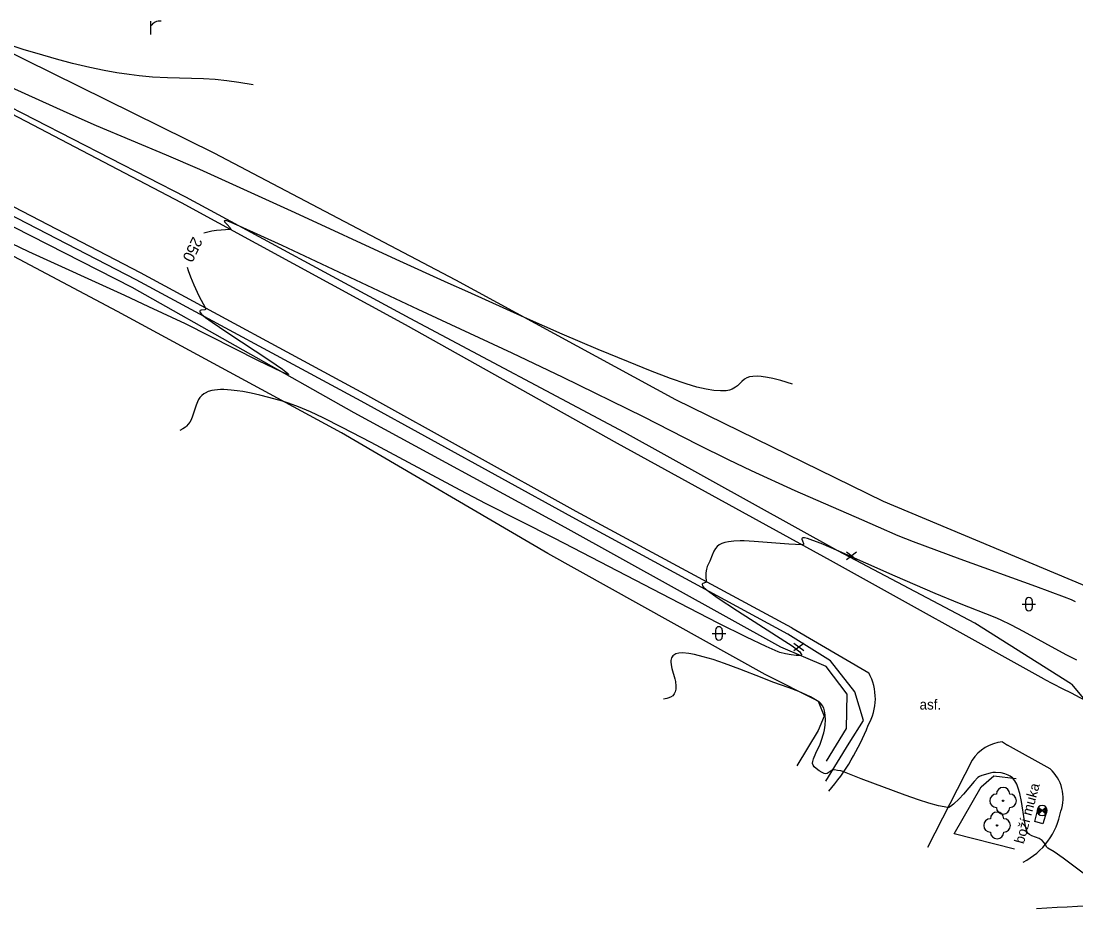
# Model space of a CAD drawing. Extents: x -593772 to -592667, y -1183541 to -1183371.
# Drawn here: x -593084.6 to -593005.8, y -1183525.4 to -1183459.1 of the extents above; entities that cross this region are included whole.
import ezdxf

# ---------------------------------------------------------------- set-up
doc = ezdxf.new("R2010")
doc.units = 0
for name, color, linetype in [('beton', 7, 'Continuous'), ('bez obruby', 7, 'Continuous'), ('hlavni vrstevnice', 7, 'Continuous'), ('popis ploch', 7, 'Continuous'), ('Statni bodove pole', 7, 'Continuous'), ('svisle dopravni znaceni', 7, 'Continuous'), ('terenni hrany', 7, 'Continuous'), ('vrstevnice', 7, 'Continuous'), ('zelen', 7, 'Continuous')]:
    doc.layers.add(name, color=color, linetype=linetype)

msp = doc.modelspace()

# ---------------------------------------------------------------- linework, layer by layer
at = {"layer": 'beton'}
for p, q in [((-593008.84, -1183518.87), (-593008.6, -1183517.98)), ((-593008.6, -1183517.98), (-593007.97, -1183518.14)), ((-593007.97, -1183518.14), (-593008.22, -1183519.03)), ((-593008.22, -1183519.03), (-593008.84, -1183518.87))]:
    msp.add_line(p, q, dxfattribs=at)
at = {"layer": 'bez obruby'}
for p, q in [((-593072.58, -1183472.63), (-593087.95, -1183464.6)), ((-593075.65, -1183477.87), (-593090.83, -1183469.97)), ((-593055.86, -1183481.76), (-593072.58, -1183472.63)), ((-593058.9, -1183486.93), (-593075.65, -1183477.87)), ((-593040, -1183490.61), (-593055.86, -1183481.76)), ((-593043.11, -1183495.69), (-593058.9, -1183486.93)), ((-593024.1, -1183499.36), (-593040, -1183490.61)), ((-593026.99, -1183504.39), (-593043.11, -1183495.69)), ((-593008.13, -1183508.23), (-593024.1, -1183499.36)), ((-593026.99, -1183504.39), (-593021.24, -1183507.75)), ((-593011.25, -1183512.92), (-593010.86, -1183513.16)), ((-593007.69, -1183514.93), (-593010.86, -1183513.16)), ((-593013.51, -1183514.29), (-593016.85, -1183520.8))]:
    msp.add_line(p, q, dxfattribs=at)
for centre, radius, start, end in [((-593024.761, -1183509.679), 4.015, 330.11001, 28.7237), ((-592925.433, -1183350.42), 178.165, 242.34407, 250.07485), ((-593037.691, -1183505.235), 17.631, 319.82198, 338.55864), ((-593010.988, -1183515.902), 2.993, 95.02863, 147.41941), ((-593009.634, -1183517.106), 2.918, 340.09281, 48.23471), ((-593012.168, -1183517.149), 5.363, 297.39756, 349.78246), ((-592999.408, -1183659.031), 133.954, 88.73466, 93.97761)]:
    msp.add_arc(centre, radius, start, end, dxfattribs=at)
at = {"layer": 'hlavni vrstevnice'}
for points in [[(-593005.791, -1183502.447), (-593006.09, -1183502.314), (-593006.613, -1183502.109), (-593008.764, -1183501.317), (-593014.41, -1183499.27), (-593017.885, -1183497.974), (-593019.03, -1183497.516), (-593020.518, -1183496.877), (-593021.746, -1183496.331), (-593026.73, -1183494.149), (-593029.991, -1183492.672), (-593031.72, -1183491.846), (-593033.989, -1183490.71), (-593038.068, -1183488.616), (-593044.076, -1183485.679), (-593047.888, -1183483.859), (-593054.898, -1183480.596), (-593065.077, -1183475.824), (-593068.255, -1183474.375), (-593069.008, -1183474.055), (-593069.21, -1183473.987), (-593069.339, -1183473.964), (-593069.388, -1183473.977), (-593069.395, -1183474.003), (-593069.36, -1183474.073), (-593069.189, -1183474.261), (-593068.944, -1183474.509), (-593068.894, -1183474.589), (-593068.897, -1183474.617), (-593068.963, -1183474.631), (-593069.964, -1183474.712), (-593070.329, -1183474.757), (-593070.729, -1183474.842), (-593070.921, -1183474.903)], [(-593072.164, -1183477.439), (-593072.096, -1183477.678), (-593071.924, -1183478.16), (-593071.672, -1183478.763), (-593071.288, -1183479.582), (-593070.808, -1183480.497), (-593070.788, -1183480.564), (-593070.8, -1183480.602), (-593070.85, -1183480.63), (-593071.13, -1183480.66), (-593071.202, -1183480.691), (-593071.224, -1183480.726), (-593071.225, -1183480.749), (-593071.191, -1183480.827), (-593071.09, -1183480.943), (-593070.789, -1183481.197), (-593070.301, -1183481.553), (-593069.203, -1183482.298), (-593065.978, -1183484.414), (-593065.031, -1183485.074), (-593064.678, -1183485.356), (-593064.601, -1183485.437), (-593064.597, -1183485.464), (-593064.639, -1183485.465), (-593064.844, -1183485.392), (-593065.124, -1183485.265), (-593066.825, -1183484.439), (-593072.302, -1183481.686), (-593075.026, -1183480.404), (-593076.823, -1183479.57), (-593083.995, -1183476.294), (-593085.926, -1183475.381)]]:
    msp.add_lwpolyline(points, dxfattribs=at)
at = {"layer": 'popis ploch'}
for p, q in [((-593074.87, -1183460.06), (-593074.87, -1183459.06)), ((-593009.77, -1183502.63), (-593008.77, -1183502.63)), ((-593009.52, -1183502.38), (-593009.52, -1183502.88)), ((-593009.02, -1183502.38), (-593009.02, -1183502.88)), ((-593032.93, -1183504.81), (-593031.93, -1183504.81)), ((-593032.68, -1183504.56), (-593032.68, -1183505.06)), ((-593032.18, -1183504.56), (-593032.18, -1183505.06))]:
    msp.add_line(p, q, dxfattribs=at)
for centre, radius, start, end in [((-593074.233, -1183459.798), 0.746, 81.32683, 148.70696), ((-593009.271, -1183502.38), 0.25, 0, 180), ((-593009.271, -1183502.88), 0.25, 180, 0), ((-593032.431, -1183504.56), 0.25, 0, 180), ((-593032.431, -1183505.06), 0.25, 180, 0)]:
    msp.add_arc(centre, radius, start, end, dxfattribs=at)
at = {"layer": 'Statni bodove pole'}
for p, q in [((-593008.545, -1183517.785), (-593008.28, -1183518.05)), ((-593008.28, -1183518.05), (-593008.545, -1183518.315)), ((-593008.015, -1183517.785), (-593008.28, -1183518.05)), ((-593008.28, -1183518.05), (-593008.015, -1183518.315))]:
    msp.add_line(p, q, dxfattribs=at)
for radius, start, end in [(0.376, 45, 135), (0.374, 135, 225), (0.304, 135, 225), (0.375, 225, 315), (0.234, 135, 225), (0.164, 135, 225), (0.0944, 135, 225), (0.0244, 135, 225), (0.0244, 315, 45), (0.0944, 315, 45), (0.164, 315, 45), (0.234, 315, 45), (0.304, 315, 45), (0.374, 315, 45)]:
    msp.add_arc((-593008.28, -1183518.05), radius, start, end, dxfattribs=at)
at = {"layer": 'svisle dopravni znaceni'}
for p, q in [((-593022.895, -1183499.281), (-593022.145, -1183498.718)), ((-593022.895, -1183498.718), (-593022.145, -1183499.281)), ((-593026.845, -1183506.101), (-593026.095, -1183505.539)), ((-593026.845, -1183505.539), (-593026.095, -1183506.101))]:
    msp.add_line(p, q, dxfattribs=at)
at = {"layer": 'terenni hrany'}
for p, q in [((-593086.28, -1183460.94), (-593070.17, -1183468.9)), ((-593072.27, -1183472.2), (-593087.77, -1183464.25)), ((-593070.17, -1183468.9), (-593052.12, -1183478.38)), ((-593076.28, -1183478.95), (-593091.61, -1183471.16)), ((-593075.97, -1183478.4), (-593091.16, -1183470.56)), ((-593077.36, -1183480.76), (-593092.47, -1183472.76)), ((-593055.51, -1183481.27), (-593072.27, -1183472.2)), ((-593059.7, -1183488.33), (-593076.28, -1183478.95)), ((-593059.17, -1183487.45), (-593075.97, -1183478.4)), ((-593052.12, -1183478.38), (-593035.68, -1183487.33)), ((-593060.64, -1183489.83), (-593077.36, -1183480.76)), ((-593039.48, -1183489.79), (-593055.51, -1183481.27)), ((-593043.39, -1183496.13), (-593059.17, -1183487.45)), ((-593035.68, -1183487.33), (-593020.17, -1183494.92)), ((-593043.93, -1183496.89), (-593059.7, -1183488.33)), ((-593045.21, -1183498.84), (-593060.64, -1183489.83)), ((-593023.56, -1183498.63), (-593039.48, -1183489.79)), ((-593020.17, -1183494.92), (-593004.23, -1183501.61)), ((-593027.28, -1183504.88), (-593043.39, -1183496.13)), ((-593027.8, -1183505.85), (-593043.93, -1183496.89)), ((-593013.32, -1183504.04), (-593023.56, -1183498.63)), ((-593028.99, -1183507.87), (-593045.21, -1183498.84)), ((-593006.09, -1183508.6), (-593013.32, -1183504.04)), ((-593024.09, -1183506.85), (-593027.28, -1183504.88)), ((-593024.43, -1183507.28), (-593027.8, -1183505.85)), ((-593022.85, -1183509.36), (-593024.43, -1183507.28)), ((-593022.27, -1183509.18), (-593024.09, -1183506.85)), ((-593025.03, -1183509.88), (-593028.99, -1183507.87)), ((-593006.09, -1183508.6), (-593005.07, -1183509.83)), ((-593022.89, -1183511.91), (-593022.85, -1183509.36)), ((-593021.63, -1183511.32), (-593022.27, -1183509.18)), ((-593025.03, -1183509.88), (-593024.58, -1183510.99)), ((-593024.58, -1183510.99), (-593025.01, -1183512.07)), ((-593022.7, -1183513.01), (-593021.63, -1183511.32)), ((-593025.01, -1183512.07), (-593026.61, -1183514.7)), ((-593024.39, -1183514.36), (-593022.89, -1183511.91)), ((-593024.45, -1183515.85), (-593022.7, -1183513.01)), ((-593012.84, -1183516.28), (-593011.9, -1183515.45)), ((-593011.9, -1183515.45), (-593010.23, -1183515.65)), ((-593014.86, -1183519.79), (-593012.84, -1183516.28)), ((-593010.36, -1183520.94), (-593014.86, -1183519.79))]:
    msp.add_line(p, q, dxfattribs=at)
at = {"layer": 'vrstevnice'}
for points in [[(-593067.233, -1183463.815), (-593068.302, -1183463.632), (-593069.213, -1183463.507), (-593070.07, -1183463.424), (-593070.951, -1183463.369), (-593073.629, -1183463.297), (-593074.748, -1183463.237), (-593075.745, -1183463.147), (-593076.49, -1183463.055), (-593077.422, -1183462.915), (-593078.367, -1183462.741), (-593079.428, -1183462.519), (-593080.735, -1183462.209), (-593081.94, -1183461.892), (-593083.382, -1183461.48), (-593084.335, -1183461.189), (-593086.284, -1183460.561)], [(-593026.944, -1183486.196), (-593027.808, -1183485.923), (-593028.412, -1183485.762), (-593028.808, -1183485.675), (-593029.272, -1183485.606), (-593029.561, -1183485.588), (-593029.911, -1183485.6), (-593030.153, -1183485.644), (-593030.35, -1183485.721), (-593030.513, -1183485.821), (-593030.716, -1183485.995), (-593031.038, -1183486.307), (-593031.184, -1183486.419), (-593031.437, -1183486.557), (-593031.647, -1183486.627), (-593031.896, -1183486.671), (-593032.31, -1183486.695), (-593032.809, -1183486.658), (-593033.394, -1183486.565), (-593034.084, -1183486.408), (-593034.891, -1183486.169), (-593036.044, -1183485.759), (-593037.543, -1183485.184), (-593039.189, -1183484.525), (-593041.458, -1183483.586), (-593044.147, -1183482.436), (-593046.949, -1183481.214), (-593051.205, -1183479.292), (-593052.657, -1183478.645), (-593056.54, -1183476.869), (-593064.088, -1183473.373), (-593071.225, -1183470.138), (-593073.718, -1183469.068), (-593078.945, -1183466.868), (-593081.132, -1183465.906), (-593087.433, -1183463.061)], [(-593005.698, -1183506.819), (-593006.484, -1183506.416), (-593009.667, -1183504.664), (-593010.578, -1183504.194), (-593011.392, -1183503.808), (-593011.804, -1183503.628), (-593014.452, -1183502.575), (-593016.265, -1183501.825), (-593019.255, -1183500.537), (-593023.66, -1183498.585), (-593024.783, -1183498.1), (-593025.406, -1183497.857), (-593025.812, -1183497.724), (-593026.041, -1183497.677), (-593026.159, -1183497.677), (-593026.211, -1183497.7), (-593026.233, -1183497.739), (-593026.234, -1183497.773), (-593026.195, -1183497.901), (-593026.119, -1183498.103), (-593026.126, -1183498.155), (-593026.151, -1183498.178), (-593026.222, -1183498.192), (-593027.199, -1183498.141), (-593029.792, -1183497.934), (-593030.555, -1183497.902), (-593030.836, -1183497.901), (-593031.331, -1183497.92), (-593031.711, -1183497.962), (-593031.98, -1183498.017), (-593032.218, -1183498.096), (-593032.414, -1183498.201), (-593032.562, -1183498.325), (-593032.683, -1183498.467), (-593032.803, -1183498.666), (-593032.935, -1183498.966), (-593033.107, -1183499.407), (-593033.216, -1183499.616), (-593033.3, -1183499.801), (-593033.359, -1183500.002), (-593033.402, -1183500.276), (-593033.413, -1183500.566), (-593033.388, -1183500.938), (-593033.396, -1183500.977), (-593033.447, -1183501.014), (-593033.644, -1183501.077), (-593033.687, -1183501.119), (-593033.693, -1183501.159), (-593033.665, -1183501.244), (-593033.589, -1183501.346), (-593033.382, -1183501.533), (-593033.215, -1183501.661), (-593032.557, -1183502.121), (-593031.037, -1183503.12), (-593026.899, -1183505.788), (-593026.578, -1183506.028), (-593026.394, -1183506.194), (-593026.302, -1183506.303), (-593026.272, -1183506.367), (-593026.272, -1183506.403), (-593026.294, -1183506.434), (-593026.359, -1183506.458), (-593026.671, -1183506.46), (-593027.034, -1183506.422), (-593027.46, -1183506.343), (-593027.875, -1183506.23), (-593028, -1183506.184), (-593028.903, -1183505.783), (-593030.368, -1183505.089), (-593032.482, -1183504.043), (-593035.373, -1183502.561), (-593043.298, -1183498.442), (-593044.75, -1183497.687), (-593049.819, -1183495.126), (-593051.766, -1183494.115), (-593058.428, -1183490.539), (-593060.581, -1183489.412), (-593062.001, -1183488.695), (-593062.939, -1183488.254), (-593063.837, -1183487.878), (-593064.605, -1183487.594), (-593065.05, -1183487.454), (-593066.066, -1183487.173), (-593066.744, -1183487.003), (-593067.394, -1183486.859), (-593068.019, -1183486.741), (-593068.442, -1183486.675), (-593068.87, -1183486.624), (-593069.432, -1183486.592), (-593069.679, -1183486.591), (-593070.131, -1183486.63), (-593070.313, -1183486.66), (-593070.587, -1183486.738), (-593070.822, -1183486.846), (-593070.913, -1183486.899), (-593071.082, -1183487.032), (-593071.214, -1183487.177), (-593071.318, -1183487.332), (-593071.401, -1183487.494), (-593071.505, -1183487.758), (-593071.765, -1183488.582), (-593071.874, -1183488.845), (-593071.967, -1183489.015), (-593072.08, -1183489.178), (-593072.221, -1183489.331), (-593072.297, -1183489.399), (-593072.489, -1183489.531), (-593072.716, -1183489.64)], [(-593004.513, -1183523.25), (-593006.701, -1183521.619), (-593007.383, -1183521.146), (-593007.855, -1183520.856), (-593007.943, -1183520.777), (-593008.043, -1183520.618), (-593008.109, -1183520.487), (-593008.279, -1183520.285), (-593008.346, -1183520.228), (-593008.514, -1183520.146), (-593009.059, -1183519.942), (-593009.228, -1183519.851), (-593009.337, -1183519.757), (-593009.4, -1183519.663), (-593009.427, -1183519.599), (-593009.504, -1183519.341), (-593009.605, -1183518.813), (-593009.837, -1183517.366), (-593009.958, -1183516.782), (-593010.072, -1183516.372), (-593010.186, -1183516.082), (-593010.335, -1183515.821), (-593010.507, -1183515.616), (-593010.663, -1183515.49), (-593010.828, -1183515.396), (-593011.072, -1183515.304), (-593011.348, -1183515.242), (-593011.768, -1183515.208), (-593011.976, -1183515.207), (-593012.162, -1183515.265), (-593012.792, -1183515.421), (-593012.972, -1183515.493), (-593013.087, -1183515.575), (-593013.374, -1183515.882), (-593014.155, -1183516.817), (-593014.477, -1183517.167), (-593014.896, -1183517.568), (-593015.129, -1183517.753), (-593015.262, -1183517.824), (-593015.318, -1183517.833), (-593016.021, -1183517.693), (-593016.744, -1183517.504), (-593017.532, -1183517.259), (-593018.524, -1183516.909), (-593021.805, -1183515.684), (-593023.184, -1183515.122), (-593023.319, -1183515.074), (-593023.578, -1183515.047), (-593023.787, -1183515.007), (-593023.931, -1183515.026), (-593023.963, -1183515.038), (-593024.336, -1183515.269), (-593024.437, -1183515.295), (-593024.564, -1183515.271), (-593024.726, -1183515.206), (-593024.945, -1183515.08), (-593025.168, -1183514.913), (-593025.311, -1183514.771), (-593025.398, -1183514.646), (-593025.432, -1183514.544), (-593025.436, -1183514.502), (-593025.425, -1183514.387), (-593025.367, -1183514.184), (-593025.182, -1183513.753), (-593024.879, -1183513.094), (-593024.786, -1183512.852), (-593024.585, -1183512.23), (-593024.534, -1183512.029), (-593024.487, -1183511.668), (-593024.466, -1183511.266), (-593024.486, -1183510.931), (-593024.539, -1183510.605), (-593024.605, -1183510.393), (-593024.695, -1183510.216), (-593024.815, -1183510.058), (-593024.956, -1183509.932), (-593025.088, -1183509.845), (-593025.595, -1183509.561), (-593026.201, -1183509.267), (-593026.471, -1183509.149), (-593027.188, -1183508.871), (-593028.406, -1183508.462), (-593029.199, -1183508.119), (-593030.864, -1183507.473), (-593032.025, -1183507.052), (-593032.865, -1183506.77), (-593033.602, -1183506.55), (-593034.253, -1183506.391), (-593034.672, -1183506.314), (-593035.149, -1183506.274), (-593035.427, -1183506.291), (-593035.646, -1183506.348), (-593035.729, -1183506.385), (-593035.812, -1183506.44), (-593035.877, -1183506.497), (-593035.928, -1183506.569), (-593035.971, -1183506.648), (-593035.997, -1183506.735), (-593036.016, -1183506.837), (-593036.02, -1183506.936), (-593036.003, -1183507.172), (-593035.95, -1183507.437), (-593035.737, -1183508.202), (-593035.688, -1183508.413), (-593035.648, -1183508.766), (-593035.655, -1183508.984), (-593035.696, -1183509.175), (-593035.774, -1183509.337), (-593035.89, -1183509.47), (-593036.046, -1183509.574), (-593036.24, -1183509.651), (-593036.334, -1183509.677), (-593036.573, -1183509.718)]]:
    msp.add_lwpolyline(points, dxfattribs=at)
at = {"layer": 'zelen'}
for centre in [(-593011.2, -1183517.32), (-593011.65, -1183519.16)]:
    msp.add_circle(centre, 0.05, dxfattribs=at)
for centre, start, end in [((-593011.7, -1183517.32), 90, 270), ((-593011.2, -1183516.82), 0, 180), ((-593010.7, -1183517.32), 270, 90), ((-593011.65, -1183518.66), 0, 180), ((-593011.2, -1183517.82), 180, 0), ((-593012.15, -1183519.16), 90, 270), ((-593011.15, -1183519.16), 270, 90), ((-593011.65, -1183519.66), 180, 0)]:
    msp.add_arc(centre, 0.5, start, end, dxfattribs=at)

# ---------------------------------------------------------------- texts
at = {"layer": 'hlavni vrstevnice'}
msp.add_text('250', height=0.8351, rotation=244.30225, dxfattribs=at).set_placement((-593071.731, -1183475.106))
at = {"layer": 'popis ploch'}
msp.add_text('asf.', height=0.75, dxfattribs=at).set_placement((-593017.443, -1183510.5))
msp.add_text('boží muka', height=0.75, rotation=74.90843, dxfattribs=at).set_placement((-593009.656, -1183520.586))

doc.saveas('drawing.dxf')
